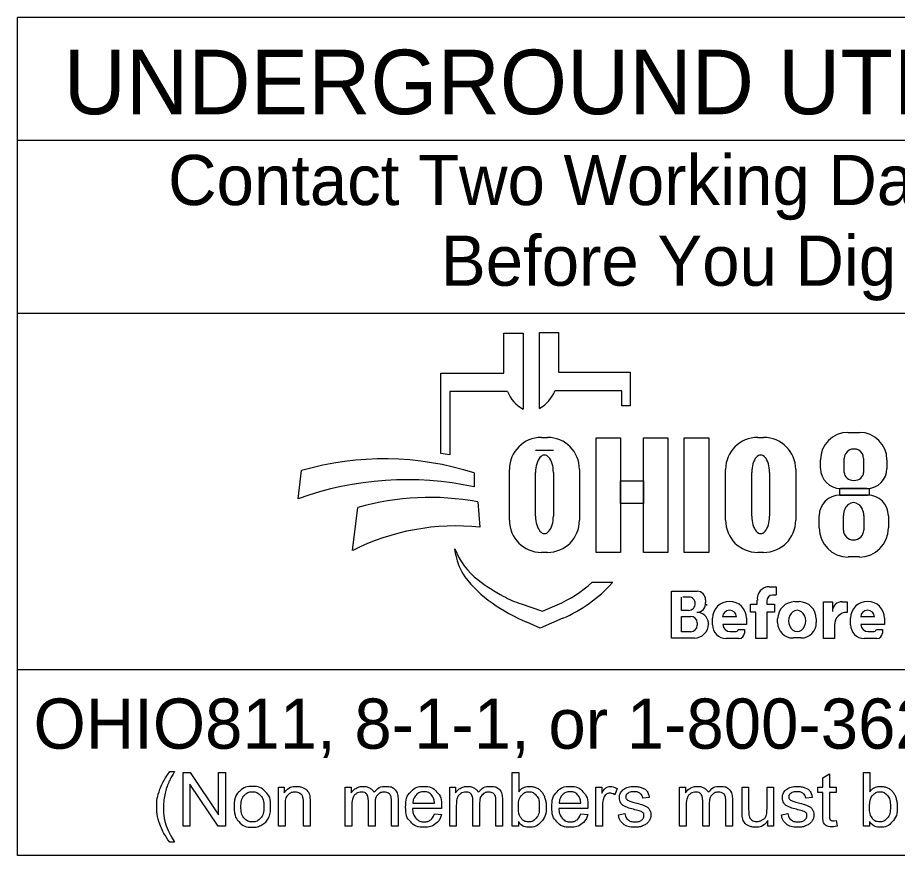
# Model space of a CAD drawing. Extents: x -8 to 42.1, y -22 to 0.
# Drawn here: x 18.773 to 21.227, y -16.266 to -13.928 of the extents above; entities that cross this region are included whole.
import ezdxf

# ---------------------------------------------------------------- set-up
doc = ezdxf.new("R2010")
doc.units = 0
doc.layers.add('SH_Data', color=7, linetype='Continuous')
doc.layers.add('SH_Text', color=7, linetype='Continuous')

msp = doc.modelspace()

# ---------------------------------------------------------------- linework, layer by layer
at = {"layer": 'SH_Data'}
for p, q in [((18.7729, -16.2657), (18.7729, -13.9282)), ((23.0229, -13.9282), (18.7729, -13.9282)), ((18.7729, -14.2697), (23.0229, -14.2697)), ((18.7729, -14.7531), (23.0229, -14.7531)), ((23.0229, -15.7478), (18.7729, -15.7478)), ((23.0229, -16.2657), (18.7729, -16.2657))]:
    msp.add_line(p, q, dxfattribs=at)
at = {"layer": 'SH_Text'}
for p, q in [((20.1289, -14.9202), (20.1289, -14.8087)), ((20.1289, -14.8087), (20.1826, -14.8087)), ((20.1826, -14.8087), (20.1826, -15.0207)), ((20.2283, -15.0184), (20.2283, -14.8064)), ((20.2283, -14.8064), (20.2819, -14.8064)), ((20.2819, -14.8064), (20.2819, -14.9178)), ((20.2819, -14.9178), (20.4811, -14.9178)), ((20.4811, -14.9178), (20.4811, -15.0117)), ((19.953, -15.1441), (19.953, -14.9202)), ((19.953, -14.9202), (20.1289, -14.9202)), ((19.9782, -14.9716), (19.9782, -15.1485)), ((20.1394, -14.9716), (19.9782, -14.9716)), ((20.4579, -14.9693), (20.2715, -14.9693)), ((20.4579, -15.0117), (20.4579, -14.9693)), ((20.4811, -15.0117), (20.4579, -15.0117)), ((21.0885, -15.0854), (21.1212, -15.0854)), ((20.2339, -15.0994), (20.2505, -15.0994)), ((20.837, -15.0994), (20.8535, -15.0994)), ((20.2672, -15.1364), (20.2174, -15.1364)), ((21.0122, -15.186), (21.0122, -15.1617)), ((21.0784, -15.1973), (21.0784, -15.1581)), ((21.1325, -15.1581), (21.1325, -15.1973)), ((21.1976, -15.1617), (21.1976, -15.186)), ((19.5556, -15.2704), (19.565, -15.1922)), ((20.0463, -15.1987), (20.0463, -15.2375)), ((20.1445, -15.3308), (20.1445, -15.1888)), ((20.2174, -15.3194), (20.2174, -15.1971)), ((20.2672, -15.1971), (20.2672, -15.3194)), ((20.3399, -15.1888), (20.3399, -15.3308)), ((20.7475, -15.3308), (20.7475, -15.1888)), ((20.8204, -15.3194), (20.8204, -15.1971)), ((20.8702, -15.1971), (20.8702, -15.3194)), ((20.943, -15.1888), (20.943, -15.3308)), ((21.0664, -15.2603), (21.1437, -15.2603)), ((21.1416, -15.242), (21.0682, -15.242)), ((20.0562, -15.2793), (20.0625, -15.3503)), ((19.7074, -15.4149), (19.7221, -15.2948)), ((21.0085, -15.3522), (21.0085, -15.3182)), ((21.076, -15.3581), (21.076, -15.3172)), ((21.1328, -15.3172), (21.1328, -15.3581)), ((21.2016, -15.3182), (21.2016, -15.3522)), ((19.9951, -15.4278), (19.9921, -15.4099)), ((20.2505, -15.4203), (20.2339, -15.4203)), ((20.8535, -15.4203), (20.837, -15.4203)), ((21.1206, -15.4331), (21.0895, -15.4331)), ((20.3754, -15.5037), (20.4329, -15.5037)), ((20.5967, -15.6594), (20.5967, -15.5287)), ((20.5967, -15.5287), (20.6679, -15.5287)), ((20.8693, -15.5159), (20.8888, -15.5159)), ((20.8888, -15.5159), (20.8888, -15.5389)), ((20.6247, -15.5822), (20.6247, -15.5452)), ((20.6499, -15.5452), (20.6286, -15.5452)), ((20.6917, -15.5525), (20.6917, -15.5604)), ((20.836, -15.5643), (20.836, -15.5538)), ((20.8621, -15.5558), (20.8621, -15.5643)), ((20.8888, -15.5394), (20.8786, -15.5394)), ((20.177, -15.564), (20.2364, -15.5845)), ((20.2364, -15.5845), (20.2775, -15.5667)), ((20.8167, -15.5873), (20.8167, -15.5643)), ((20.8167, -15.5643), (20.836, -15.5643)), ((20.8621, -15.5643), (20.8837, -15.5643)), ((20.8837, -15.5643), (20.8837, -15.5873)), ((20.9405, -15.5577), (20.9527, -15.5577)), ((21.0208, -15.6606), (21.0208, -15.5579)), ((21.0208, -15.5579), (21.0453, -15.5579)), ((21.0453, -15.5579), (21.0453, -15.5848)), ((21.0726, -15.5579), (21.0864, -15.5579)), ((21.0864, -15.5579), (21.0864, -15.5876)), ((20.2937, -15.6041), (20.2304, -15.6316)), ((20.6441, -15.5822), (20.6247, -15.5822)), ((20.6247, -15.6416), (20.6247, -15.5987)), ((20.6247, -15.5987), (20.6502, -15.5987)), ((20.7113, -15.6226), (20.7113, -15.6042)), ((20.7778, -15.6003), (20.7393, -15.6003)), ((20.8058, -15.6042), (20.8058, -15.6219)), ((20.8316, -15.5873), (20.8167, -15.5873)), ((20.8316, -15.6606), (20.8316, -15.5873)), ((20.8837, -15.5873), (20.8621, -15.5873)), ((20.8621, -15.5873), (20.8621, -15.6606)), ((20.8927, -15.6163), (20.8927, -15.6055)), ((21.0005, -15.6055), (21.0005, -15.6163)), ((21.0962, -15.6226), (21.0962, -15.6042)), ((21.1628, -15.6003), (21.1242, -15.6003)), ((21.1907, -15.6042), (21.1907, -15.6219)), ((20.2304, -15.6316), (20.1931, -15.6151)), ((20.6683, -15.6168), (20.6683, -15.6232)), ((20.6997, -15.6197), (20.6997, -15.6201)), ((20.8058, -15.6219), (20.7394, -15.6219)), ((21.0513, -15.6225), (21.0513, -15.6606)), ((21.1907, -15.6219), (21.1243, -15.6219)), ((20.65, -15.6416), (20.6247, -15.6416)), ((20.7603, -15.6411), (20.7744, -15.6411)), ((20.783, -15.6356), (20.7999, -15.6356)), ((20.7999, -15.6356), (20.7999, -15.6454)), ((21.1452, -15.6411), (21.1593, -15.6411)), ((21.1679, -15.6356), (21.1848, -15.6356)), ((21.1848, -15.6356), (21.1848, -15.6454)), ((20.6604, -15.6594), (20.5967, -15.6594)), ((20.7846, -15.6606), (20.7492, -15.6606)), ((20.8621, -15.6606), (20.8316, -15.6606)), ((20.9577, -15.6591), (20.9355, -15.6591)), ((21.0513, -15.6606), (21.0208, -15.6606)), ((21.1696, -15.6606), (21.1342, -15.6606))]:
    msp.add_line(p, q, dxfattribs=at)
for points in [[(20.3864, -15.1004), (20.4543, -15.1004), (20.4543, -15.4204), (20.3864, -15.4204)], [(20.5185, -15.1004), (20.5865, -15.1004), (20.5865, -15.4204), (20.5185, -15.4204)], [(20.6318, -15.1004), (20.7006, -15.1004), (20.7006, -15.4204), (20.6318, -15.4204)], [(20.4543, -15.2203), (20.5185, -15.2203), (20.5185, -15.2843), (20.4543, -15.2843)], [(21.066, -15.2419), (21.1477, -15.2419), (21.1477, -15.2604), (21.066, -15.2604)]]:
    msp.add_lwpolyline(points, close=True, dxfattribs=at)
for points in [[(19.1975, -16.0319), (19.2107, -16.0319)], [(19.2343, -16.1845), (19.2343, -16.0344), (19.2546, -16.0344), (19.3336, -16.1523), (19.3336, -16.0344), (19.3526, -16.0344), (19.3526, -16.1845), (19.3323, -16.1845), (19.2533, -16.0666), (19.2533, -16.1845), (19.2343, -16.1845)], [(20.1697, -16.1845), (20.1527, -16.1845), (20.1527, -16.0344), (20.1711, -16.0344), (20.1711, -16.0879)], [(21.0187, -16.1527), (21.0187, -16.09), (21.0051, -16.09), (21.0051, -16.0757), (21.0187, -16.0757), (21.0187, -16.0488), (21.0371, -16.0377), (21.0371, -16.0757), (21.0555, -16.0757), (21.0555, -16.09), (21.0371, -16.09), (21.0371, -16.1538)], [(21.1488, -16.1845), (21.1317, -16.1845), (21.1317, -16.0344), (21.1502, -16.0344), (21.1502, -16.0879)], [(19.5002, -16.1845), (19.5002, -16.0757), (19.5168, -16.0757), (19.5168, -16.0912)], [(19.6866, -16.1845), (19.6866, -16.0757), (19.7031, -16.0757), (19.7031, -16.0911)], [(19.978, -16.1845), (19.978, -16.0757), (19.9945, -16.0757), (19.9945, -16.0911)], [(20.3858, -16.1845), (20.3858, -16.0757), (20.4024, -16.0757), (20.4024, -16.0922)], [(20.4449, -16.0792), (20.4384, -16.0963)], [(20.619, -16.1845), (20.619, -16.0757), (20.6355, -16.0757), (20.6355, -16.0911)], [(20.7933, -16.1431), (20.7933, -16.0757), (20.8118, -16.0757), (20.8118, -16.136)], [(20.863, -16.134), (20.863, -16.0757), (20.8815, -16.0757), (20.8815, -16.1845), (20.865, -16.1845)], [(19.5886, -16.1177), (19.5886, -16.1845), (19.5702, -16.1845), (19.5702, -16.1184)], [(19.7697, -16.1214), (19.7697, -16.1845), (19.7513, -16.1845), (19.7513, -16.1139)], [(19.8342, -16.1099), (19.8342, -16.1845), (19.8157, -16.1845), (19.8157, -16.116)], [(19.8753, -16.1198), (19.936, -16.1198)], [(20.0611, -16.1214), (20.0611, -16.1845), (20.0427, -16.1845), (20.0427, -16.1139)], [(20.1255, -16.1099), (20.1255, -16.1845), (20.1071, -16.1845), (20.1071, -16.116)], [(20.2833, -16.1198), (20.344, -16.1198)], [(20.5348, -16.1039), (20.5167, -16.1063)], [(20.7021, -16.1214), (20.7021, -16.1845), (20.6837, -16.1845), (20.6837, -16.1139)], [(20.7665, -16.1099), (20.7665, -16.1845), (20.7481, -16.1845), (20.7481, -16.116)], [(20.9894, -16.1039), (20.9713, -16.1063)], [(19.5187, -16.1252), (19.5187, -16.1845), (19.5002, -16.1845)], [(19.7051, -16.1281), (19.7051, -16.1845), (19.6866, -16.1845)], [(19.9554, -16.1349), (19.8742, -16.1349)], [(19.9964, -16.1281), (19.9964, -16.1845), (19.978, -16.1845)], [(20.3634, -16.1349), (20.2822, -16.1349)], [(20.4042, -16.1276), (20.4042, -16.1845), (20.3858, -16.1845)], [(20.6374, -16.1281), (20.6374, -16.1845), (20.619, -16.1845)], [(19.9358, -16.1494), (19.9549, -16.1518)], [(20.3438, -16.1494), (20.3629, -16.1518)], [(20.4484, -16.152), (20.4666, -16.1492)], [(20.865, -16.1845), (20.865, -16.1685)], [(20.903, -16.152), (20.9212, -16.1492)], [(21.0555, -16.1681), (21.0582, -16.1844)], [(20.1697, -16.1709), (20.1697, -16.1845)], [(21.1488, -16.1709), (21.1488, -16.1845)], [(19.2107, -16.2287), (19.1975, -16.2287)]]:
    msp.add_lwpolyline(points, dxfattribs=at)
for centre, radius, start, end in [((20.2307, -14.9348), 0.0985, 201.9296, 240.7469), ((20.1801, -14.9325), 0.0985, 299.2531, 338.0704), ((21.0885, -15.1617), 0.0763, 90, 180), ((21.1212, -15.1617), 0.0763, 0, 90), ((20.2339, -15.1888), 0.0895, 90, 180), ((20.2505, -15.1888), 0.0895, 0, 90), ((20.837, -15.1888), 0.0895, 90, 180), ((20.8535, -15.1888), 0.0895, 0, 90), ((19.7951, -15.9783), 0.8191, 72.1402, 106.3144), ((19.8249, -15.953), 0.8191, 79.2074, 81.0007), ((21.0682, -15.186), 0.056, 180, 270), ((21.1416, -15.186), 0.056, 270, 0), ((19.8582, -16.1094), 0.8919, 77.8238, 109.8274), ((21.0664, -15.3182), 0.0579, 90, 180), ((21.1437, -15.3182), 0.0579, 0, 90), ((19.9221, -15.9991), 0.7322, 79.44, 105.8467), ((20.2339, -15.3308), 0.0895, 180, 270), ((20.2505, -15.3308), 0.0895, 270, 0), ((20.837, -15.3308), 0.0895, 180, 270), ((20.8535, -15.3308), 0.0895, 270, 0), ((19.9941, -15.9823), 0.6357, 83.8248, 116.8021), ((21.0895, -15.3522), 0.081, 180, 270), ((21.1206, -15.3522), 0.081, 270, 0), ((20.1795, -15.3378), 0.2008, 201.0457, 232.5314), ((20.1364, -15.4037), 0.1433, 189.6817, 216.0884), ((20.2701, -15.3062), 0.3088, 216.0884, 235.7167), ((20.372, -15.0865), 0.5173, 232.5314, 241.794), ((20.1341, -15.2363), 0.3602, 293.4582, 312.0712), ((20.1341, -15.2363), 0.401, 293.4582, 317.8286), ((20.6679, -15.5525), 0.0238, 0, 90), ((20.8693, -15.5494), 0.0335, 90, 187.5187), ((20.2868, -15.2454), 0.3371, 241.794, 250.9821), ((20.646, -15.5621), 0.0169, 357.8325, 90), ((20.8786, -15.5558), 0.0165, 90, 180), ((20.4366, -15.062), 0.6044, 235.7167, 246.2325), ((20.6441, -15.5634), 0.0187, 270, 2.0582), ((20.6675, -15.5632), 0.0243, 270, 6.6529), ((20.6781, -15.5647), 0.0175, 347.4023, 0), ((20.7585, -15.6042), 0.0473, 0, 180), ((20.9405, -15.6055), 0.0478, 90, 180), ((20.9527, -15.6055), 0.0478, 0, 90), ((21.0722, -15.5848), 0.0269, 89.2449, 180), ((21.1435, -15.6042), 0.0473, 0, 180), ((20.6502, -15.6168), 0.0181, 0, 90), ((20.6676, -15.6196), 0.0321, 4.0748, 90), ((20.7586, -15.6012), 0.0193, 2.9632, 177.0368), ((21.0862, -15.6225), 0.0349, 89.6033, 180), ((21.1435, -15.6012), 0.0193, 2.9632, 177.0368), ((20.65, -15.6232), 0.0184, 270, 0), ((20.6604, -15.6201), 0.0393, 270, 0), ((20.6668, -15.6197), 0.033, 0, 11.7502), ((20.7492, -15.6226), 0.038, 180, 270), ((20.7603, -15.6201), 0.021, 184.827, 270), ((20.9355, -15.6163), 0.0428, 180, 270), ((20.9577, -15.6163), 0.0428, 270, 0), ((21.1342, -15.6226), 0.038, 180, 270), ((21.1452, -15.6201), 0.021, 184.827, 270), ((20.7744, -15.6318), 0.00938, 270, 335.9979), ((20.7846, -15.6454), 0.0152, 270, 0), ((21.1593, -15.6318), 0.00938, 270, 335.9979), ((21.1696, -15.6454), 0.0152, 270, 0)]:
    msp.add_arc(centre, radius, start, end, dxfattribs=at)
for centre, major_axis, ratio, start_param, end_param in [((21.1054, -15.1581), (0.0271, 0), 0.969373, 0, 3.141593), ((20.2423, -15.1971), (0, 0.0484), 0.514403, 4.712389, 7.853982), ((20.8453, -15.1971), (0, 0.0484), 0.514403, 4.712389, 7.853982), ((21.1054, -15.1973), (0.0271, 0), 0.818453, 3.141593, 6.283185), ((21.1044, -15.3172), (0, 0.0358), 0.794529, 4.712389, 7.853982), ((20.2423, -15.3194), (0, 0.0484), 0.514403, 1.570796, 4.712389), ((20.8453, -15.3194), (0, 0.0484), 0.514403, 1.570796, 4.712389), ((21.1044, -15.3581), (0.0284, 0), 0.959837, 3.141593, 6.283185), ((20.9471, -15.6109), (0, 0.029), 0.832186, 4.712389, 7.853982), ((20.9471, -15.6109), (0, 0.0302), 0.797287, 1.570796, 4.712389)]:
    msp.add_ellipse(centre, major_axis=major_axis, ratio=ratio, start_param=start_param, end_param=end_param, dxfattribs=at)
for points in [[(19.1975, -16.2287), (19.1823, -16.2095), (19.1717, -16.1837), (19.1611, -16.1578), (19.1611, -16.1302), (19.1611, -16.1058), (19.169, -16.0835), (19.1783, -16.0576), (19.1975, -16.0319)], [(19.2107, -16.0319), (19.1983, -16.0532), (19.1943, -16.0623), (19.1881, -16.0764), (19.1845, -16.0918), (19.1801, -16.1109), (19.1801, -16.1303), (19.1801, -16.1796), (19.2107, -16.2287)], [(19.3768, -16.1301), (19.3768, -16.0999), (19.3935, -16.0854), (19.4076, -16.0733), (19.4277, -16.0733), (19.4502, -16.0733), (19.4644, -16.088), (19.4786, -16.1027), (19.4786, -16.1286), (19.4786, -16.1496), (19.4723, -16.1616), (19.466, -16.1736), (19.454, -16.1803), (19.442, -16.1869), (19.4277, -16.1869), (19.4049, -16.1869), (19.3908, -16.1723), (19.3768, -16.1577), (19.3768, -16.1301)], [(19.3958, -16.1301), (19.3958, -16.151), (19.4048, -16.1614), (19.4139, -16.1718), (19.4277, -16.1718), (19.4414, -16.1718), (19.4505, -16.1614), (19.4596, -16.1509), (19.4596, -16.1295), (19.4596, -16.1093), (19.4505, -16.0989), (19.4413, -16.0885), (19.4277, -16.0885), (19.4139, -16.0885), (19.4048, -16.0989), (19.3958, -16.1092), (19.3958, -16.1301)], [(19.5168, -16.0912), (19.5288, -16.0733), (19.5514, -16.0733), (19.5613, -16.0733), (19.5695, -16.0768), (19.5777, -16.0804), (19.5818, -16.0861), (19.5859, -16.0918), (19.5876, -16.0997), (19.5886, -16.1049), (19.5886, -16.1177)], [(19.5702, -16.1184), (19.5702, -16.1071), (19.568, -16.1016), (19.5659, -16.096), (19.5604, -16.0927), (19.5549, -16.0893), (19.5475, -16.0893), (19.5358, -16.0893), (19.5272, -16.0968), (19.5187, -16.1043), (19.5187, -16.1252)], [(19.7031, -16.0911), (19.7083, -16.0831), (19.7168, -16.0782), (19.7253, -16.0733), (19.7361, -16.0733), (19.7482, -16.0733), (19.756, -16.0783), (19.7637, -16.0834), (19.7669, -16.0924), (19.7798, -16.0733), (19.8005, -16.0733), (19.8167, -16.0733), (19.8254, -16.0823), (19.8342, -16.0912), (19.8342, -16.1099)], [(19.7513, -16.1139), (19.7513, -16.1016), (19.7468, -16.0955), (19.7423, -16.0893), (19.732, -16.0893), (19.7242, -16.0893), (19.7176, -16.0934), (19.711, -16.0975), (19.708, -16.1054), (19.7051, -16.1133), (19.7051, -16.1281)], [(19.8157, -16.116), (19.8157, -16.105), (19.8139, -16.1001), (19.8122, -16.0953), (19.8074, -16.0923), (19.8027, -16.0893), (19.7964, -16.0893), (19.7849, -16.0893), (19.7773, -16.097), (19.7697, -16.1046), (19.7697, -16.1214)], [(19.9549, -16.1518), (19.9504, -16.1685), (19.9382, -16.1777), (19.926, -16.1869), (19.9071, -16.1869), (19.8832, -16.1869), (19.8692, -16.1723), (19.8552, -16.1576), (19.8552, -16.131), (19.8552, -16.1036), (19.8694, -16.0885), (19.8835, -16.0733), (19.906, -16.0733), (19.9278, -16.0733), (19.9417, -16.0882), (19.9555, -16.103), (19.9555, -16.13), (19.9555, -16.1316), (19.9554, -16.1349)], [(19.936, -16.1198), (19.9348, -16.106), (19.9291, -16.0991), (19.9203, -16.0884), (19.9062, -16.0884), (19.8935, -16.0884), (19.8849, -16.0969), (19.8762, -16.1055), (19.8753, -16.1198)], [(19.9945, -16.0911), (19.9996, -16.0831), (20.0081, -16.0782), (20.0166, -16.0733), (20.0275, -16.0733), (20.0396, -16.0733), (20.0473, -16.0783), (20.0551, -16.0834), (20.0582, -16.0924), (20.0712, -16.0733), (20.0919, -16.0733), (20.1081, -16.0733), (20.1168, -16.0823), (20.1255, -16.0912), (20.1255, -16.1099)], [(20.0427, -16.1139), (20.0427, -16.1016), (20.0382, -16.0955), (20.0337, -16.0893), (20.0234, -16.0893), (20.0156, -16.0893), (20.009, -16.0934), (20.0024, -16.0975), (19.9994, -16.1054), (19.9964, -16.1133), (19.9964, -16.1281)], [(20.1071, -16.116), (20.1071, -16.105), (20.1053, -16.1001), (20.1035, -16.0953), (20.0988, -16.0923), (20.0941, -16.0893), (20.0877, -16.0893), (20.0763, -16.0893), (20.0687, -16.097), (20.0611, -16.1046), (20.0611, -16.1214)], [(20.1695, -16.1293), (20.1695, -16.1489), (20.1748, -16.1576), (20.1835, -16.1718), (20.1983, -16.1718), (20.2104, -16.1718), (20.2192, -16.1613), (20.228, -16.1508), (20.228, -16.13), (20.228, -16.1087), (20.2196, -16.0986), (20.2111, -16.0884), (20.1992, -16.0884), (20.1871, -16.0884), (20.1783, -16.0989), (20.1695, -16.1094), (20.1695, -16.1293)], [(20.1711, -16.0879), (20.1828, -16.0733), (20.2009, -16.0733), (20.2109, -16.0733), (20.2199, -16.0773), (20.2289, -16.0814), (20.2346, -16.0887), (20.2404, -16.096), (20.2437, -16.1064), (20.247, -16.1167), (20.247, -16.1285), (20.247, -16.1564), (20.2332, -16.1717), (20.2193, -16.1869), (20.2, -16.1869), (20.1807, -16.1869), (20.1697, -16.1709)], [(20.3629, -16.1518), (20.3584, -16.1685), (20.3462, -16.1777), (20.334, -16.1869), (20.3151, -16.1869), (20.2912, -16.1869), (20.2772, -16.1723), (20.2632, -16.1576), (20.2632, -16.131), (20.2632, -16.1036), (20.2774, -16.0885), (20.2915, -16.0733), (20.314, -16.0733), (20.3358, -16.0733), (20.3497, -16.0882), (20.3635, -16.103), (20.3635, -16.13), (20.3635, -16.1316), (20.3634, -16.1349)], [(20.344, -16.1198), (20.3428, -16.106), (20.3371, -16.0991), (20.3282, -16.0884), (20.3142, -16.0884), (20.3015, -16.0884), (20.2928, -16.0969), (20.2842, -16.1055), (20.2833, -16.1198)], [(20.4024, -16.0922), (20.4087, -16.0807), (20.4141, -16.077), (20.4195, -16.0733), (20.4259, -16.0733), (20.4352, -16.0733), (20.4449, -16.0792)], [(20.4384, -16.0963), (20.4317, -16.0923), (20.4249, -16.0923), (20.4189, -16.0923), (20.4141, -16.0959), (20.4093, -16.0996), (20.4073, -16.106), (20.4042, -16.1159), (20.4042, -16.1276)], [(20.5167, -16.1063), (20.5155, -16.0978), (20.5096, -16.0931), (20.5037, -16.0884), (20.4929, -16.0884), (20.4802, -16.0884), (20.4748, -16.0926), (20.4693, -16.0968), (20.4693, -16.1025), (20.4693, -16.1061), (20.4716, -16.1089), (20.4739, -16.1119), (20.4787, -16.1139), (20.4814, -16.1149), (20.495, -16.1186), (20.5146, -16.1238), (20.5223, -16.1271), (20.5301, -16.1304), (20.5345, -16.1368), (20.5389, -16.1431), (20.5389, -16.1526), (20.5389, -16.1618), (20.5335, -16.1699), (20.5282, -16.178), (20.518, -16.1825), (20.5078, -16.1869), (20.495, -16.1869), (20.4738, -16.1869), (20.4626, -16.1781), (20.4515, -16.1693), (20.4484, -16.152)], [(20.4666, -16.1492), (20.4681, -16.1601), (20.4752, -16.166), (20.4822, -16.1718), (20.4949, -16.1718), (20.5076, -16.1718), (20.5138, -16.1667), (20.5199, -16.1615), (20.5199, -16.1545), (20.5199, -16.1482), (20.5145, -16.1447), (20.5107, -16.1422), (20.4956, -16.1384), (20.4753, -16.1333), (20.4674, -16.1295), (20.4596, -16.1258), (20.4555, -16.1192), (20.4515, -16.1126), (20.4515, -16.1046), (20.4515, -16.0974), (20.4548, -16.0912), (20.4582, -16.085), (20.4639, -16.0809), (20.4682, -16.0777), (20.4757, -16.0755), (20.4831, -16.0733), (20.4916, -16.0733), (20.5044, -16.0733), (20.5141, -16.077), (20.5238, -16.0807), (20.5284, -16.087), (20.5331, -16.0933), (20.5348, -16.1039)], [(20.6355, -16.0911), (20.6406, -16.0831), (20.6491, -16.0782), (20.6576, -16.0733), (20.6685, -16.0733), (20.6806, -16.0733), (20.6883, -16.0783), (20.6961, -16.0834), (20.6992, -16.0924), (20.7122, -16.0733), (20.7329, -16.0733), (20.7491, -16.0733), (20.7578, -16.0823), (20.7665, -16.0912), (20.7665, -16.1099)], [(20.6837, -16.1139), (20.6837, -16.1016), (20.6792, -16.0955), (20.6747, -16.0893), (20.6644, -16.0893), (20.6566, -16.0893), (20.65, -16.0934), (20.6434, -16.0975), (20.6404, -16.1054), (20.6374, -16.1133), (20.6374, -16.1281)], [(20.7481, -16.116), (20.7481, -16.105), (20.7463, -16.1001), (20.7445, -16.0953), (20.7398, -16.0923), (20.7351, -16.0893), (20.7287, -16.0893), (20.7173, -16.0893), (20.7097, -16.097), (20.7021, -16.1046), (20.7021, -16.1214)], [(20.9713, -16.1063), (20.9701, -16.0978), (20.9642, -16.0931), (20.9583, -16.0884), (20.9475, -16.0884), (20.9348, -16.0884), (20.9294, -16.0926), (20.9239, -16.0968), (20.9239, -16.1025), (20.9239, -16.1061), (20.9262, -16.1089), (20.9284, -16.1119), (20.9333, -16.1139), (20.936, -16.1149), (20.9496, -16.1186), (20.9691, -16.1238), (20.9769, -16.1271), (20.9847, -16.1304), (20.9891, -16.1368), (20.9935, -16.1431), (20.9935, -16.1526), (20.9935, -16.1618), (20.9881, -16.1699), (20.9827, -16.178), (20.9726, -16.1825), (20.9624, -16.1869), (20.9496, -16.1869), (20.9283, -16.1869), (20.9172, -16.1781), (20.9061, -16.1693), (20.903, -16.152)], [(20.9212, -16.1492), (20.9227, -16.1601), (20.9298, -16.166), (20.9368, -16.1718), (20.9494, -16.1718), (20.9622, -16.1718), (20.9683, -16.1667), (20.9745, -16.1615), (20.9745, -16.1545), (20.9745, -16.1482), (20.9691, -16.1447), (20.9652, -16.1422), (20.9502, -16.1384), (20.9299, -16.1333), (20.922, -16.1295), (20.9142, -16.1258), (20.9101, -16.1192), (20.9061, -16.1126), (20.9061, -16.1046), (20.9061, -16.0974), (20.9094, -16.0912), (20.9127, -16.085), (20.9185, -16.0809), (20.9228, -16.0777), (20.9302, -16.0755), (20.9377, -16.0733), (20.9462, -16.0733), (20.959, -16.0733), (20.9687, -16.077), (20.9784, -16.0807), (20.983, -16.087), (20.9876, -16.0933), (20.9894, -16.1039)], [(21.1486, -16.1293), (21.1486, -16.1489), (21.1539, -16.1576), (21.1626, -16.1718), (21.1774, -16.1718), (21.1895, -16.1718), (21.1983, -16.1613), (21.2071, -16.1508), (21.2071, -16.13), (21.2071, -16.1087), (21.1986, -16.0986), (21.1902, -16.0884), (21.1782, -16.0884), (21.1662, -16.0884), (21.1574, -16.0989), (21.1486, -16.1094), (21.1486, -16.1293)], [(21.1502, -16.0879), (21.1618, -16.0733), (21.18, -16.0733), (21.19, -16.0733), (21.199, -16.0773), (21.2079, -16.0814), (21.2137, -16.0887), (21.2195, -16.096), (21.2228, -16.1064), (21.226, -16.1167), (21.226, -16.1285), (21.226, -16.1564), (21.2122, -16.1717), (21.1984, -16.1869), (21.179, -16.1869), (21.1598, -16.1869), (21.1488, -16.1709)], [(19.8742, -16.1349), (19.8753, -16.1528), (19.8844, -16.1623), (19.8935, -16.1718), (19.9071, -16.1718), (19.9173, -16.1718), (19.9245, -16.1665), (19.9316, -16.1611), (19.9358, -16.1494)], [(20.2822, -16.1349), (20.2833, -16.1528), (20.2924, -16.1623), (20.3015, -16.1718), (20.3151, -16.1718), (20.3253, -16.1718), (20.3325, -16.1665), (20.3396, -16.1611), (20.3438, -16.1494)], [(20.865, -16.1685), (20.8523, -16.1869), (20.8305, -16.1869), (20.8209, -16.1869), (20.8125, -16.1833), (20.8042, -16.1796), (20.8001, -16.174), (20.7961, -16.1684), (20.7945, -16.1603), (20.7933, -16.1549), (20.7933, -16.1431)], [(20.8118, -16.136), (20.8118, -16.1505), (20.8129, -16.1555), (20.8146, -16.1627), (20.8203, -16.1669), (20.8259, -16.171), (20.8342, -16.171), (20.8425, -16.171), (20.8497, -16.1668), (20.857, -16.1625), (20.86, -16.1552), (20.863, -16.1479), (20.863, -16.134)], [(21.0582, -16.1844), (21.0504, -16.186), (21.0442, -16.186), (21.0342, -16.186), (21.0287, -16.1828), (21.0232, -16.1797), (21.0209, -16.1745), (21.0187, -16.1693), (21.0187, -16.1527)], [(21.0371, -16.1538), (21.0371, -16.1617), (21.0381, -16.1639), (21.039, -16.1662), (21.0412, -16.1675), (21.0434, -16.1689), (21.0475, -16.1689), (21.0505, -16.1689), (21.0555, -16.1681)]]:
    msp.add_open_spline(points, degree=3, dxfattribs=at)

# ---------------------------------------------------------------- texts
for s, height, p in [('UNDERGROUND UTILITIES', 0.18, (18.9011, -14.1978)), ('Contact Two Working Days', 0.14, (19.1926, -14.4513)), ('Before You Dig', 0.14, (19.9537, -14.6763)), ('OHIO811, 8-1-1, or 1-800-362-2764', 0.14, (18.8174, -15.9679))]:
    msp.add_text(s, height=height, dxfattribs=at).set_placement(p)

doc.saveas('drawing.dxf')
